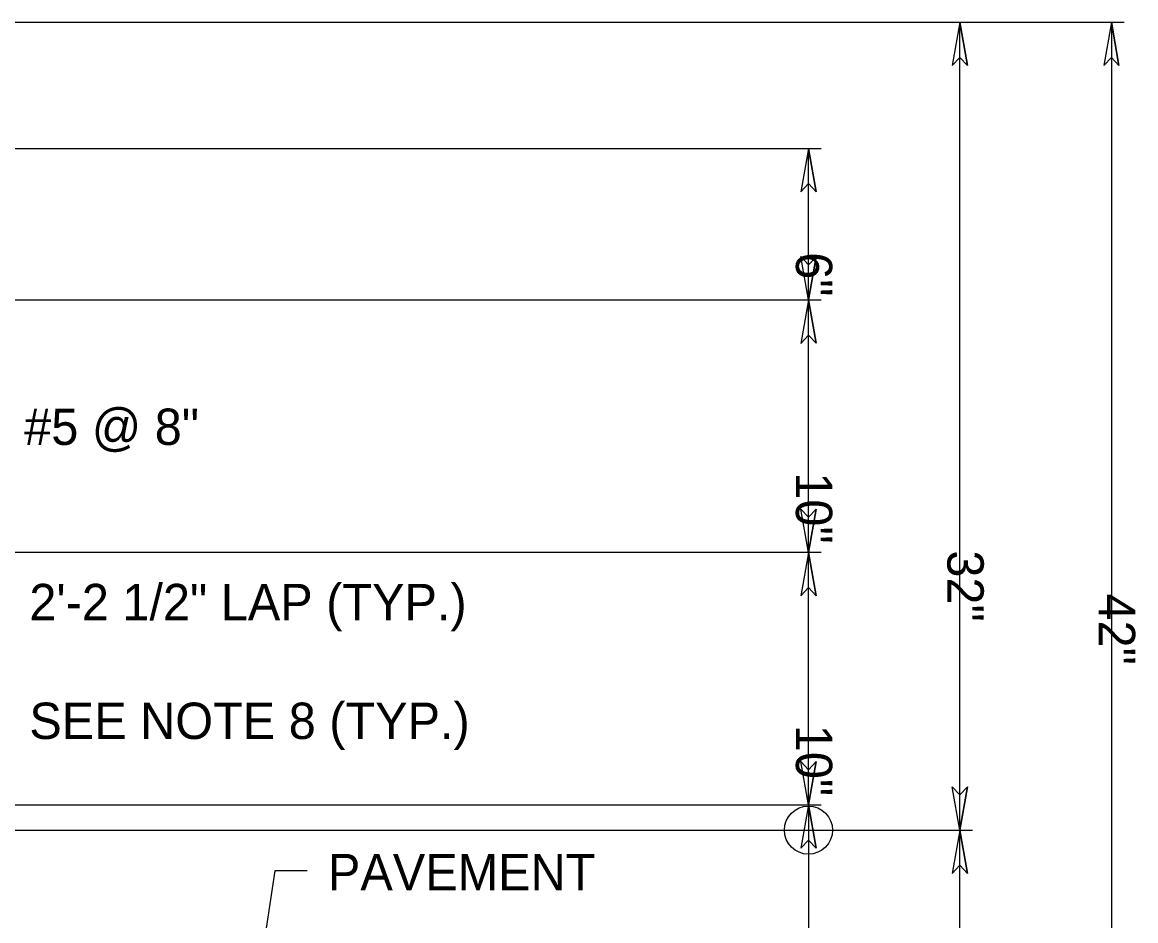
# Model space of a CAD drawing. Extents: x -26.46 to -19.21, y -3.62 to 6.25.
# Drawn here: x -22.246 to -20.409, y 3.682 to 5.165 of the extents above; entities that cross this region are included whole.
import ezdxf

# ---------------------------------------------------------------- set-up
doc = ezdxf.new("R2010")
doc.units = 0
for name, color, linetype in [('ANNO-WOUT', 7, 'Continuous'), ('DETL-DIMS', 7, 'Continuous'), ('Level 10', 7, 'Continuous'), ('Level 12', 7, 'Continuous')]:
    doc.layers.add(name, color=color, linetype=linetype)

msp = doc.modelspace()

# ---------------------------------------------------------------- linework, layer by layer
at = {"layer": 'ANNO-WOUT'}
msp.add_circle((-20.9488, 3.8313), 0.0397, dxfattribs=at)
at = {"layer": 'DETL-DIMS'}
for p, q in [((-20.6988, 5.1646), (-20.7115, 5.0931)), ((-20.6988, 5.1646), (-20.6863, 5.0931)), ((-20.4488, 5.1646), (-20.4615, 5.0931)), ((-20.4488, 5.1646), (-20.4363, 5.0931)), ((-20.6988, 5.1066), (-20.7115, 5.0931)), ((-20.6863, 5.0931), (-20.6988, 5.1066)), ((-20.4488, 5.1066), (-20.4615, 5.0931)), ((-20.4363, 5.0931), (-20.4488, 5.1066)), ((-20.9488, 4.9563), (-20.9615, 4.8847)), ((-20.9488, 4.9563), (-20.9363, 4.8848)), ((-20.9488, 4.8983), (-20.9615, 4.8847)), ((-20.9363, 4.8848), (-20.9488, 4.8983)), ((-20.9488, 4.7063), (-20.9615, 4.7778)), ((-20.9488, 4.7643), (-20.9615, 4.7778)), ((-20.9488, 4.7063), (-20.9363, 4.7777)), ((-20.9363, 4.7777), (-20.9488, 4.7643)), ((-20.9488, 4.7063), (-20.9615, 4.6347)), ((-20.9488, 4.7063), (-20.9363, 4.6348)), ((-20.9488, 4.6483), (-20.9615, 4.6347)), ((-20.9363, 4.6348), (-20.9488, 4.6483)), ((-20.9488, 4.2896), (-20.9615, 4.3611)), ((-20.9488, 4.3476), (-20.9615, 4.3611)), ((-20.9488, 4.2896), (-20.9363, 4.3611)), ((-20.9363, 4.3611), (-20.9488, 4.3476)), ((-20.9488, 4.2896), (-20.9615, 4.2181)), ((-20.9488, 4.2896), (-20.9363, 4.2181)), ((-20.9488, 4.2316), (-20.9615, 4.2181)), ((-20.9363, 4.2181), (-20.9488, 4.2316)), ((-20.9488, 3.8729), (-20.9615, 3.9444)), ((-20.9488, 3.9309), (-20.9615, 3.9444)), ((-20.9488, 3.8729), (-20.9363, 3.9444)), ((-20.9363, 3.9444), (-20.9488, 3.9309)), ((-20.6988, 3.8313), (-20.7115, 3.9028)), ((-20.6988, 3.8893), (-20.7115, 3.9028)), ((-20.6988, 3.8313), (-20.6863, 3.9027)), ((-20.6863, 3.9027), (-20.6988, 3.8893)), ((-20.9488, 3.8729), (-20.9615, 3.8014)), ((-20.9488, 3.8729), (-20.9363, 3.8014)), ((-20.6988, 3.8313), (-20.7115, 3.7597)), ((-20.6988, 3.8313), (-20.6863, 3.7598)), ((-20.9488, 3.8149), (-20.9615, 3.8014)), ((-20.9363, 3.8014), (-20.9488, 3.8149)), ((-20.6988, 3.7733), (-20.7115, 3.7597)), ((-20.6863, 3.7598), (-20.6988, 3.7733))]:
    msp.add_line(p, q, dxfattribs=at)
for points in [[(-20.6863, 5.0931), (-20.6988, 5.1646), (-20.7115, 5.0931), (-20.6988, 5.1066)], [(-20.4363, 5.0931), (-20.4488, 5.1646), (-20.4615, 5.0931), (-20.4488, 5.1066)], [(-20.9363, 4.8848), (-20.9488, 4.9563), (-20.9615, 4.8847), (-20.9488, 4.8983)], [(-20.9363, 4.7777), (-20.9488, 4.7063), (-20.9615, 4.7778), (-20.9488, 4.7643)], [(-20.9363, 4.6348), (-20.9488, 4.7063), (-20.9615, 4.6347), (-20.9488, 4.6483)], [(-20.9363, 4.3611), (-20.9488, 4.2896), (-20.9615, 4.3611), (-20.9488, 4.3476)], [(-20.9363, 4.2181), (-20.9488, 4.2896), (-20.9615, 4.2181), (-20.9488, 4.2316)], [(-20.9363, 3.9444), (-20.9488, 3.8729), (-20.9615, 3.9444), (-20.9488, 3.9309)], [(-20.6863, 3.9027), (-20.6988, 3.8313), (-20.7115, 3.9028), (-20.6988, 3.8893)], [(-20.9363, 3.8014), (-20.9488, 3.8729), (-20.9615, 3.8014), (-20.9488, 3.8149)], [(-20.6863, 3.7598), (-20.6988, 3.8313), (-20.7115, 3.7597), (-20.6988, 3.7733)]]:
    msp.add_lwpolyline(points, close=True, dxfattribs=at)
at = {"layer": 'Level 10'}
for p, q in [((-22.7361, 5.1646), (-20.428, 5.1646)), ((-20.6988, 3.8327), (-20.6988, 5.1646)), ((-20.4488, 5.1646), (-20.4488, 3.4146)), ((-22.8614, 4.9563), (-20.928, 4.9562)), ((-20.9488, 4.7063), (-20.9488, 4.9563)), ((-22.8334, 4.7063), (-20.928, 4.7063)), ((-20.9488, 4.2896), (-20.9488, 4.7063)), ((-20.928, 4.2896), (-22.8155, 4.2896)), ((-20.9488, 3.8729), (-20.9488, 4.2896)), ((-22.7716, 3.8729), (-20.928, 3.8729)), ((-20.9488, 3.8729), (-20.9488, 3.4146)), ((-22.5963, 3.8313), (-20.678, 3.8313)), ((-20.6988, 3.5396), (-20.6988, 3.8327)), ((-21.8298, 3.7639), (-21.8801, 3.4324)), ((-21.776, 3.7639), (-21.8298, 3.7639))]:
    msp.add_line(p, q, dxfattribs=at)

# ---------------------------------------------------------------- texts
at = {"layer": 'Level 12'}
for s, p in [('6"', (-20.9696, 4.7851)), ('10"', (-20.9696, 4.4218)), ('32"', (-20.7196, 4.293)), ('42"', (-20.4696, 4.2218)), ('10"', (-20.9696, 4.0051))]:
    msp.add_text(s, height=0.06001, rotation=270, dxfattribs=at).set_placement(p)
for s, p in [('#5 @ 8"', (-22.2431, 4.467)), ('2\'-2 1/2" LAP (TYP.)', (-22.2347, 4.1777)), ('SEE NOTE 8 (TYP.)', (-22.2347, 3.9817)), ('PAVEMENT ', (-21.7419, 3.732))]:
    msp.add_text(s, height=0.06001, dxfattribs=at).set_placement(p)

doc.saveas('drawing.dxf')
